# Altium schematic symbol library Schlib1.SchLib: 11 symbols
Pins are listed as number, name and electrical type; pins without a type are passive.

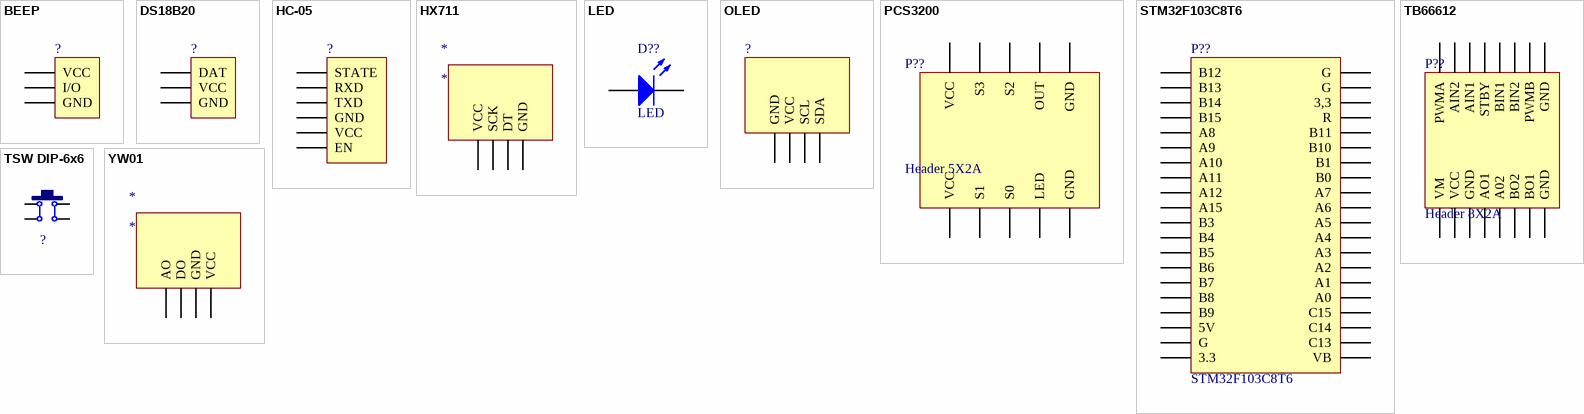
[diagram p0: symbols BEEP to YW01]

## BEEP
designator ?  (value not drawn)
BEEP, 3-Pin
footprint HDR2.54-M-LI-3P (排母，3脚   淘宝ID:黄晶宝石   店铺网址:https://shop463601444.taobao.com)
pins: 1 VCC, 2 I/O, 3 GND

## DS18B20
designator ?, comment ?  (value not drawn)
DS18B20, 3-Pin
footprint HDR2.54-M-LI-3P (排母，3脚   淘宝ID:黄晶宝石   店铺网址:https://shop463601444.taobao.com)
pins: 1 DAT, 2 VCC, 3 GND

## HC-05
designator ?  (value not drawn)
HC-05, 6-Pin
footprint HDR2.54-M-LI-6P (排母，6脚  淘宝ID:黄晶宝石   店铺网址:https://shop463601444.taobao.com)
pins: 1 STATE, 2 RXD, 3 TXD, 4 GND, 5 VCC, 6 EN

## HX711
designator *
HX711,4-Pin
footprint HDR2.54-M-LI-4P (排母，4脚  淘宝ID:黄晶宝石   店铺网址:https://shop463601444.taobao.com)
pins: 1 VCC, 2 SCK, 3 DT, 4 GND

## LED
designator D??
Typical INFRARED GaAs LED
simulation model LED0 (Diode)
footprint LED 5MM-R (红色5mm直插LED)
pins: 1 A, 2 K

## OLED
designator ?, comment OLED0.96  (value not drawn)
OLED0.96,4-Pin
footprint HDR2.54-M-LI-4P (排母，4脚  淘宝ID:黄晶宝石   店铺网址:https://shop463601444.taobao.com)
pins: 1 GND, 2 VCC, 3 SCL, 4 SDA

## PCS3200
designator P??, comment Header 5X2A
PCS3200, 10-Pin, Dual row
signal-integrity model Connector
footprint HDR2.54-M-LI-5*2P
pins: 1 VCC, 2 S1, 3 S0, 4 LED, 5 GND, 6 VCC, 7 S3, 8 S2, 9 OUT, 10 GND

## STM32F103C8T6
designator P??
最小系统板
signal-integrity model Connector
footprint DIP40-600_MH (带底座 52*15.2*4mm(长宽高))
pins: 1 B12, 2 B13, 3 B14, 4 B15, 5 A8, 6 A9, 7 A10, 8 A11, 9 A12, 10 A15, 11 B3, 12 B4, 13 B5, 14 B6, 15 B7, 16 B8, 17 B9, 18 5V, 19 G, 20 3.3, 21 VB, 22 C13, 23 C14, 24 C15, 25 A0, 26 A1, 27 A2, 28 A3, 29 A4, 30 A5, 31 A6, 32 A7, 33 B0, 34 B1, 35 B10, 36 B11, 37 R, 38 3,3, 39 G, 40 G

## TB66612
designator P??, comment Header 8X2A
TB66612,16-Pin
signal-integrity model Connector
footprint HDR2.54-M-LI-8*2P (排母，8*2脚)
pins: 1 VM, 2 VCC, 3 GND, 4 AO1, 5 A02, 6 BO2, 7 BO1, 8 GND, 9 PWMA, 10 AIN2, 11 AIN1, 12 STBY, 13 BIN1, 14 BIN2, 15 PWMB, 16 GND

## TSW DIP-6x6
designator ?  (value not drawn)
直插6*6*5轻触开关; BOM名称: 直插12x12轻触开关; 版权归属: 封装库来自淘宝 ID：黄晶宝石
footprint TSW DIP-6*6*6 (6*6*6mm)
pins: 1, 2, 3, 4

## YW01
designator *
YW01,4-Pin
footprint HDR2.54-M-LI-4P (排母，4脚  淘宝ID:黄晶宝石   店铺网址:https://shop463601444.taobao.com)
pins: 1 AO, 2 DO, 3 GND, 4 VCC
